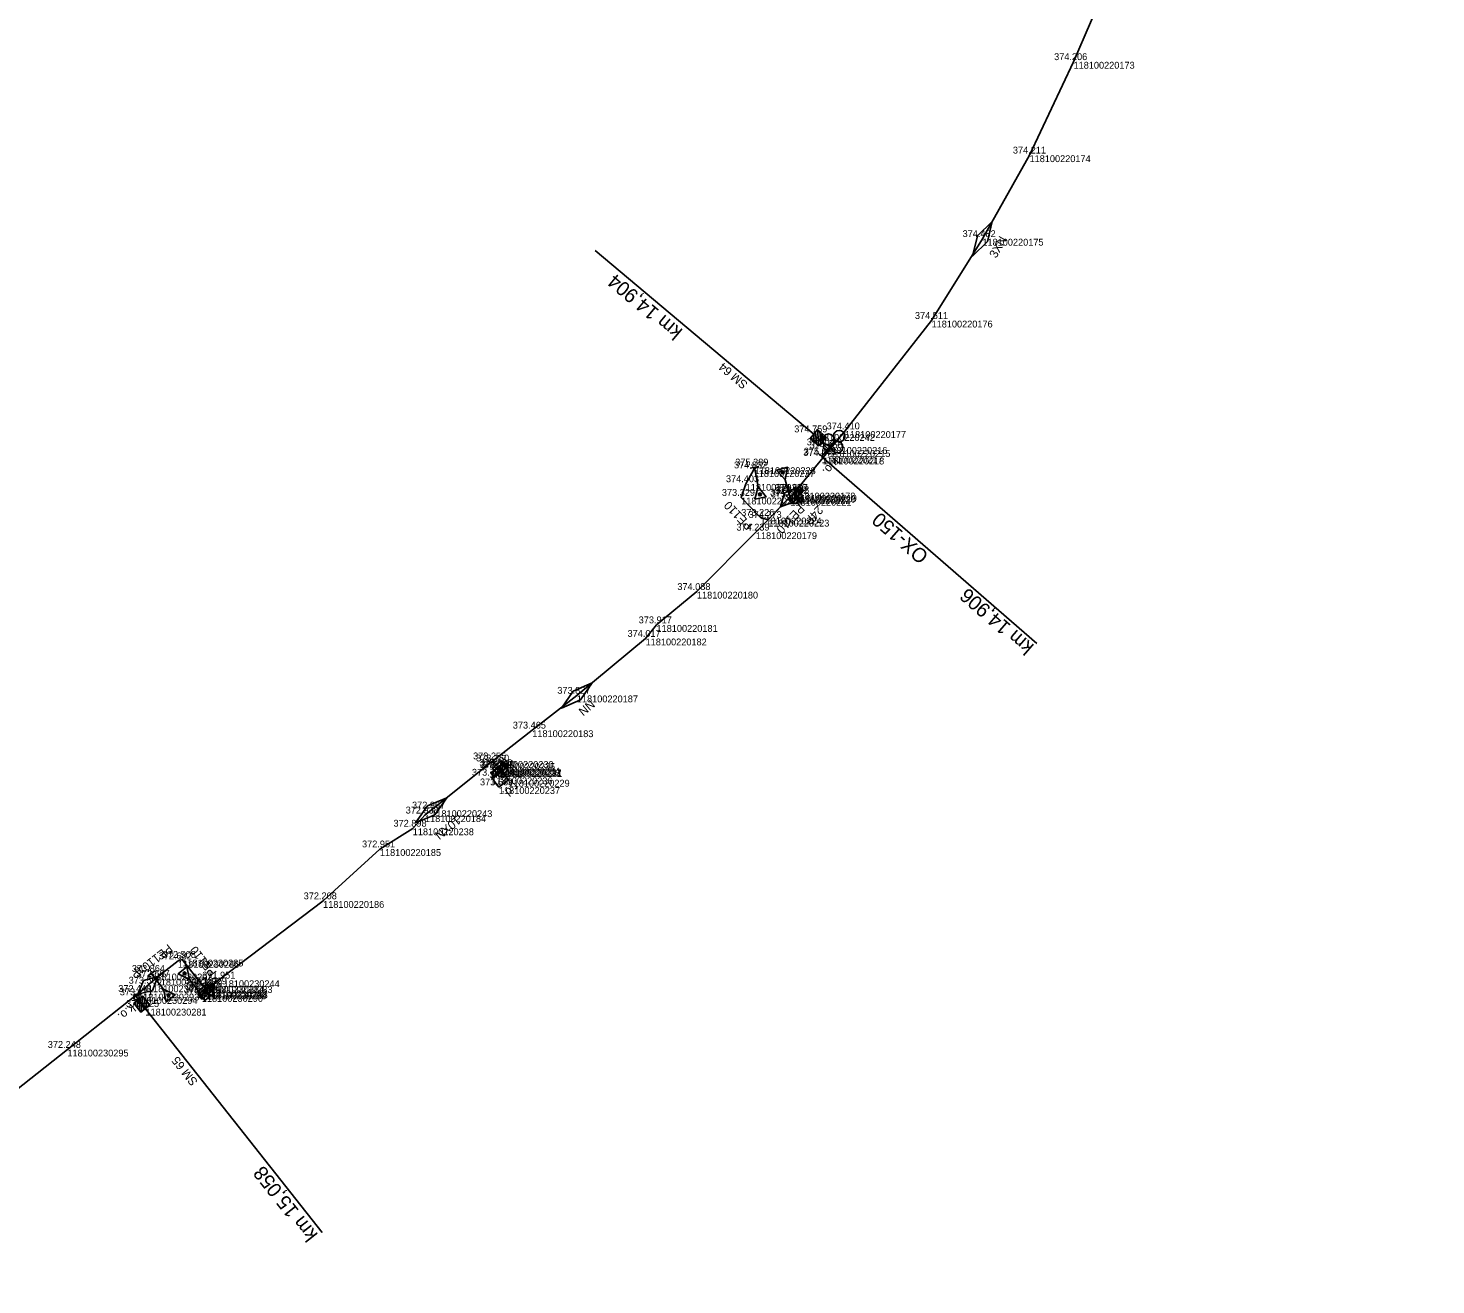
# Model space of a CAD drawing. Extents: x -732194 to -724760, y -944826 to -941477.
# Drawn here: x -731076.7 to -730830.1, y -942059.1 to -941838.8 of the extents above; entities that cross this region are included whole.
import ezdxf

# ---------------------------------------------------------------- set-up
doc = ezdxf.new("R2010")
doc.units = 0
for name, color, linetype in [('Vrstva 26', 7, 'Continuous'), ('Vrstva 28', 7, 'Continuous'), ('Vrstva 3', 7, 'Continuous'), ('Vrstva 31', 7, 'Continuous'), ('Vrstva 33', 7, 'Continuous'), ('Vrstva 35', 7, 'Continuous'), ('Vrstva 36', 7, 'Continuous'), ('Vrstva 4', 7, 'Continuous'), ('Vrstva 60', 7, 'Continuous'), ('Vrstva 61', 7, 'Continuous'), ('Vrstva 8', 7, 'Continuous')]:
    doc.layers.add(name, color=color, linetype=linetype)

msp = doc.modelspace()

# ---------------------------------------------------------------- linework, layer by layer
at = {"layer": 'Vrstva 26'}
for points in [[(-730884.6, -941823.97), (-730893.54, -941844.74), (-730901.25, -941861.12), (-730909.51, -941875.76), (-730918.42, -941890.11), (-730933.6, -941909.47), (-730936.34, -941912.8), (-730937.42, -941914.12), (-730942.48, -941920.27)], [(-730942.48, -941920.27), (-730943.32, -941921.07), (-730947.04, -941925.01), (-730949.2, -941927.21), (-730959.53, -941937.62), (-730966.61, -941943.46), (-730968.52, -941945.84), (-730980.57, -941955.82), (-730988.38, -941961.92), (-730995.35, -941967.32), (-730995.09, -941967.68), (-730994.25, -941968.5), (-730994.17, -941968.84)], [(-730977.88, -941953.59), (-730979.94, -941956.59), (-730983.27, -941958.05), (-730981.21, -941955.05), (-730977.88, -941953.59)]]:
    msp.add_lwpolyline(points, dxfattribs=at)
at = {"layer": 'Vrstva 28'}
for p, q in [((-730936.83, -941912.23), (-730936.89, -941912.3)), ((-730940.92, -941918.54), (-730945.71, -941923.61)), ((-730944.16, -941920.27), (-730941.72, -941919.38)), ((-730941.72, -941919.38), (-730942.47, -941921.87)), ((-730941.75, -941919.41), (-730941.7, -941920.83)), ((-730941.37, -941919.38), (-730941.33, -941920.44)), ((-730944.91, -941922.76), (-730944.16, -941920.27)), ((-730942.47, -941921.87), (-730944.91, -941922.76)), ((-730943.55, -941921.35), (-730943.55, -941921.45)), ((-730943.19, -941920.97), (-730943.16, -941921.81)), ((-730942.83, -941920.58), (-730942.78, -941921.99)), ((-730942.48, -941920.27), (-730942.21, -941920.65)), ((-730942.47, -941920.19), (-730942.42, -941921.6)), ((-730942.11, -941919.8), (-730942.06, -941921.22)), ((-730940.98, -941919.74), (-730940.97, -941920.05)), ((-730994.77, -941968.68), (-730994.93, -941970.09)), ((-730994.36, -941968.35), (-730994.51, -941969.75)), ((-730993.94, -941968.02), (-730994.1, -941969.42)), ((-730993.53, -941967.69), (-730993.69, -941969.09)), ((-730993.16, -941967.71), (-730993.27, -941968.76)), ((-730992.82, -941968.12), (-730992.86, -941968.43)), ((-730995.6, -941969.34), (-730995.61, -941969.44)), ((-730995.19, -941969.01), (-730995.28, -941969.85)), ((-731058.34, -942008.96), (-731053.11, -942004.33)), ((-731056.49, -942005.77), (-731053.98, -942005.1)), ((-731053.98, -942005.1), (-731054.95, -942007.52)), ((-731057.47, -942008.18), (-731056.49, -942005.77)), ((-731054.95, -942007.52), (-731057.47, -942008.18)), ((-731046.86, -942008.2), (-731046.87, -942008.3)), ((-731046.44, -942007.87), (-731046.54, -942008.71)), ((-731046.03, -942007.54), (-731046.19, -942008.95)), ((-731045.61, -942007.21), (-731045.77, -942008.62)), ((-731045.6, -942007.51), (-731045.43, -942007.71)), ((-731045.19, -942006.88), (-731045.36, -942008.29)), ((-731044.78, -942006.56), (-731044.94, -942007.96)), ((-731044.4, -942006.58), (-731044.53, -942007.63)), ((-731044.07, -942007), (-731044.11, -942007.3)), ((-731057.71, -942008.65), (-731057.79, -942008.71)), ((-731057.75, -942008.68), (-731056.16, -942010.73))]:
    msp.add_line(p, q, dxfattribs=at)
for points in [[(-730936.34, -941912.8), (-730933.6, -941909.47), (-730918.42, -941890.11), (-730909.51, -941875.76), (-730901.25, -941861.12), (-730893.54, -941844.74), (-730884.6, -941823.97), (-730884.81, -941823.92), (-730891.53, -941820.91), (-730888.73, -941813.4), (-730882.1, -941797.64), (-730879.51, -941791.69), (-730868.59, -941766.2), (-730855.72, -941741.09), (-730846.98, -941727.15), (-730841.76, -941718.5), (-730840.09, -941716.56), (-730834.08, -941707.22), (-730832.47, -941708.21), (-730830.06, -941709.33)], [(-730937.42, -941914.12), (-730936.34, -941912.8), (-730936.86, -941912.27), (-730939.07, -941909.99)], [(-730943.32, -941921.07), (-730942.48, -941920.27), (-730937.42, -941914.12), (-730937.69, -941913.9)], [(-730947.04, -941925.01), (-730948.39, -941924.63), (-730951.78, -941921.13), (-730950.98, -941918.73), (-730949.59, -941916.31), (-730949.43, -941915.81)], [(-730995.35, -941967.32), (-730988.38, -941961.92), (-730980.57, -941955.82), (-730968.52, -941945.84), (-730966.61, -941943.46), (-730959.53, -941937.62), (-730949.2, -941927.21), (-730947.04, -941925.01), (-730943.32, -941921.07), (-730943.16, -941921.36)], [(-730940.78, -941921.31), (-730941.85, -941920.99), (-730941.46, -941922.04)], [(-731044.61, -942006.77), (-731043.35, -942005.75), (-731025.03, -941991.84), (-731015.08, -941982.75), (-731009.32, -941979.12), (-731007.18, -941976.81), (-731006.09, -941975.94), (-730995.35, -941967.32), (-730995.09, -941967.68), (-730994.25, -941968.5), (-730994.17, -941968.84)], [(-730992.84, -941969.7), (-730993.86, -941969.23), (-730993.63, -941970.32)], [(-731054.37, -942005.45), (-731050.45, -942002.36), (-731049.71, -942002.12), (-731046.09, -942006.71), (-731044.61, -942006.77)], [(-731057.45, -942008.09), (-731055.72, -942006.64), (-731054.37, -942005.45), (-731055.13, -942004.57)], [(-731120.63, -942059.14), (-731119.86, -942058.33), (-731114.37, -942053.86), (-731113.43, -942053.2), (-731112.54, -942052.04), (-731090.85, -942034.48), (-731069.83, -942017.9), (-731057.45, -942008.09), (-731057.75, -942008.68)], [(-731044.61, -942006.77), (-731045.6, -942007.51), (-731046.28, -942008.33)], [(-731044.1, -942008.57), (-731045.12, -942008.1), (-731044.89, -942009.19)]]:
    msp.add_lwpolyline(points, dxfattribs=at)
for points in [[(-730940.82, -941919.89), (-730942.87, -941922.09), (-730943.6, -941921.4), (-730941.56, -941919.21)], [(-730992.69, -941968.29), (-730995.03, -941970.17), (-730995.66, -941969.39), (-730993.31, -941967.51)], [(-731043.94, -942007.17), (-731046.29, -942009.03), (-731046.91, -942008.24), (-731044.56, -942006.38)]]:
    msp.add_lwpolyline(points, close=True, dxfattribs=at)
for centre in [(-730936.86, -941912.27), (-731057.75, -942008.68)]:
    msp.add_circle(centre, 0.5, dxfattribs=at)
at = {"layer": 'Vrstva 3'}
for p, q in [((-730977.36, -941877.83), (-730939.07, -941909.99)), ((-730938.18, -941912.04), (-730938.42, -941909.22)), ((-730937.84, -941911.63), (-730938.02, -941909.56)), ((-730939.4, -941911.01), (-730939.45, -941910.44)), ((-730938.99, -941911.35), (-730939.11, -941910.03)), ((-730938.59, -941911.7), (-730938.77, -941909.63)), ((-730937.5, -941911.22), (-730937.61, -941909.9)), ((-730937.16, -941910.82), (-730937.21, -941910.24)), ((-731057.86, -942009.53), (-731057.93, -942010.1)), ((-731057.45, -942009.2), (-731057.6, -942010.52)), ((-731057.03, -942008.87), (-731057.27, -942010.93)), ((-731056.61, -942008.54), (-731056.94, -942011.35)), ((-731056.29, -942008.96), (-731056.53, -942011.02)), ((-731055.96, -942009.37), (-731056.11, -942010.69)), ((-731055.63, -942009.79), (-731055.69, -942010.36)), ((-731025.19, -942049.98), (-731056.16, -942010.73))]:
    msp.add_line(p, q, dxfattribs=at)
for points in [[(-730939.71, -941910.75), (-730938.42, -941909.22), (-730936.89, -941910.51), (-730938.18, -941912.04)], [(-731055.37, -942010.11), (-731056.94, -942011.35), (-731058.18, -942009.78), (-731056.61, -942008.54)]]:
    msp.add_lwpolyline(points, close=True, dxfattribs=at)
at = {"layer": 'Vrstva 31'}
for points in [[(-730884.6, -941823.97), (-730893.54, -941844.74), (-730901.25, -941861.12), (-730909.51, -941875.76), (-730918.42, -941890.11), (-730933.6, -941909.47), (-730936.34, -941912.8), (-730937.42, -941914.12), (-730942.48, -941920.27), (-730942.41, -941920.81)], [(-730911.23, -941878.8), (-730910.38, -941875.26), (-730907.79, -941872.71), (-730908.64, -941876.25), (-730911.23, -941878.8)], [(-730942.48, -941920.27), (-730943.32, -941921.07), (-730947.04, -941925.01), (-730949.2, -941927.21), (-730959.53, -941937.62), (-730966.61, -941943.46), (-730968.52, -941945.84), (-730980.57, -941955.82), (-730988.38, -941961.92), (-730995.35, -941967.32), (-730995.09, -941967.68), (-730994.25, -941968.5), (-730993.96, -941968.69)], [(-730995.35, -941967.32), (-731006.09, -941975.94), (-731007.18, -941976.81), (-731009.32, -941979.12), (-731015.08, -941982.75), (-731025.03, -941991.84), (-731043.35, -942005.75), (-731044.61, -942006.77), (-731045.6, -942007.51), (-731045.61, -942007.87)], [(-731008.82, -941978.13), (-731006.71, -941975.16), (-731003.36, -941973.75), (-731005.46, -941976.72), (-731008.82, -941978.13)], [(-731044.61, -942006.77), (-731046.09, -942006.71), (-731049.71, -942002.12), (-731050.45, -942002.36), (-731054.37, -942005.45), (-731055.72, -942006.64), (-731057.45, -942008.09)], [(-731057.45, -942008.09), (-731069.83, -942017.9), (-731090.85, -942034.48), (-731112.54, -942052.04), (-731113.43, -942053.2), (-731114.37, -942053.86), (-731119.86, -942058.33), (-731120.63, -942059.14)]]:
    msp.add_lwpolyline(points, dxfattribs=at)
at = {"layer": 'Vrstva 33'}
for p, q in [((-730942.03, -941921.14), (-730942.78, -941920.47)), ((-730941.7, -941920.77), (-730942.37, -941921.52)), ((-730993.65, -941969.08), (-730994.28, -941968.3)), ((-730993.26, -941968.77), (-730994.04, -941969.39)), ((-731045.3, -942008.26), (-731045.92, -942007.48)), ((-731044.91, -942007.95), (-731045.69, -942008.57))]:
    msp.add_line(p, q, dxfattribs=at)
for points in [[(-730940.99, -941920.74), (-730942.33, -941922.22), (-730943.82, -941920.88), (-730942.48, -941919.4), (-730940.99, -941920.74)], [(-730992.56, -941968.84), (-730994.12, -941970.1), (-730995.37, -941968.54), (-730993.81, -941967.28), (-730992.56, -941968.84)], [(-731044.21, -942008.04), (-731045.78, -942009.28), (-731047.02, -942007.71), (-731045.45, -942006.47), (-731044.21, -942008.04)]]:
    msp.add_lwpolyline(points, dxfattribs=at)
at = {"layer": 'Vrstva 35'}
for p, q in [((-730948.39, -941924.63), (-730951.78, -941921.13)), ((-730947.04, -941925.01), (-730943.32, -941921.07)), ((-731054.37, -942005.45), (-731050.45, -942002.36)), ((-731049.71, -942002.12), (-731046.09, -942006.71))]:
    msp.add_line(p, q, dxfattribs=at)
at = {"layer": 'Vrstva 36'}
msp.add_lwpolyline([(-730993.85, -941968.89), (-730995.54, -941970.18), (-730994.22, -941971.88), (-730992.54, -941970.6)], close=True, dxfattribs=at)
at = {"layer": 'Vrstva 4'}
for p, q in [((-730948.66, -941915.67), (-730950.19, -941915.96)), ((-730944.61, -941916.92), (-730944.36, -941916.49)), ((-730948.34, -941920.36), (-730948.62, -941920.76)), ((-730943.91, -941921.57), (-730942.41, -941921.16)), ((-731054.52, -942004.09), (-731055.74, -942005.05)), ((-731049.33, -942004.79), (-731049.27, -942004.3)), ((-731052.08, -942008.12), (-731052.14, -942008.6)), ((-731046.89, -942008.81), (-731045.66, -942007.85))]:
    msp.add_line(p, q, dxfattribs=at)
for points in [[(-730949.43, -941915.81), (-730948.77, -941919.23), (-730947.42, -941921.01), (-730949.38, -941921.39), (-730948.77, -941919.23)], [(-730943.16, -941921.36), (-730944.09, -941918.01), (-730945.58, -941916.34), (-730943.65, -941915.8), (-730944.09, -941918.01)], [(-731055.13, -942004.57), (-731052.98, -942007.31), (-731050.96, -942008.27), (-731052.53, -942009.51), (-731052.98, -942007.31)], [(-731046.28, -942008.33), (-731048.43, -942005.6), (-731050.44, -942004.63), (-731048.88, -942003.39), (-731048.43, -942005.6)]]:
    msp.add_lwpolyline(points, dxfattribs=at)
for centre in [(-730944.48, -941916.71), (-730948.48, -941920.56), (-731049.3, -942004.54), (-731052.11, -942008.36)]:
    msp.add_circle(centre, 0.248, dxfattribs=at)
at = {"layer": 'Vrstva 60'}
for p, q in [((-730893.54, -941844.74), (-730893.54, -941844.74)), ((-730901.25, -941861.12), (-730901.25, -941861.12)), ((-730909.51, -941875.76), (-730909.51, -941875.76)), ((-730918.42, -941890.11), (-730918.42, -941890.11)), ((-730933.6, -941909.47), (-730933.6, -941909.47)), ((-730939.07, -941909.99), (-730939.07, -941909.99)), ((-730937.69, -941913.9), (-730937.69, -941913.9)), ((-730937.42, -941914.12), (-730937.42, -941914.12)), ((-730936.86, -941912.27), (-730936.86, -941912.27)), ((-730936.34, -941912.8), (-730936.34, -941912.8)), ((-730949.59, -941916.31), (-730949.59, -941916.31)), ((-730949.43, -941915.81), (-730949.43, -941915.81)), ((-730950.98, -941918.73), (-730950.98, -941918.73)), ((-730951.78, -941921.13), (-730951.78, -941921.13)), ((-730943.32, -941921.07), (-730943.32, -941921.07)), ((-730943.16, -941921.36), (-730943.16, -941921.36)), ((-730942.48, -941920.27), (-730942.48, -941920.27)), ((-730942.41, -941920.81), (-730942.41, -941920.81)), ((-730942.21, -941920.65), (-730942.21, -941920.65)), ((-730948.39, -941924.63), (-730948.39, -941924.63)), ((-730947.04, -941925.01), (-730947.04, -941925.01)), ((-730949.2, -941927.21), (-730949.2, -941927.21)), ((-730959.53, -941937.62), (-730959.53, -941937.62)), ((-730966.61, -941943.46), (-730966.61, -941943.46)), ((-730968.52, -941945.84), (-730968.52, -941945.84)), ((-730980.57, -941955.82), (-730980.57, -941955.82)), ((-730988.38, -941961.92), (-730988.38, -941961.92)), ((-730995.35, -941967.32), (-730995.35, -941967.32)), ((-730995.09, -941967.68), (-730995.09, -941967.68)), ((-730994.25, -941968.5), (-730994.25, -941968.5)), ((-730993.96, -941968.69), (-730993.96, -941968.69)), ((-730995.54, -941970.18), (-730995.54, -941970.18)), ((-730994.17, -941968.84), (-730994.17, -941968.84)), ((-730993.85, -941968.89), (-730993.85, -941968.89)), ((-730992.54, -941970.6), (-730992.54, -941970.6)), ((-730994.22, -941971.88), (-730994.22, -941971.88)), ((-731006.09, -941975.94), (-731006.09, -941975.94)), ((-731007.18, -941976.81), (-731007.18, -941976.81)), ((-731009.32, -941979.12), (-731009.32, -941979.12)), ((-731015.08, -941982.75), (-731015.08, -941982.75)), ((-731025.03, -941991.84), (-731025.03, -941991.84)), ((-731050.45, -942002.36), (-731050.45, -942002.36)), ((-731049.71, -942002.12), (-731049.71, -942002.12)), ((-731055.13, -942004.57), (-731055.13, -942004.57)), ((-731054.37, -942005.45), (-731054.37, -942005.45)), ((-731043.35, -942005.75), (-731043.35, -942005.75)), ((-731057.45, -942008.09), (-731057.45, -942008.09)), ((-731055.72, -942006.64), (-731055.72, -942006.64)), ((-731046.09, -942006.71), (-731046.09, -942006.71)), ((-731045.61, -942007.87), (-731045.61, -942007.87)), ((-731045.6, -942007.51), (-731045.6, -942007.51)), ((-731045.43, -942007.71), (-731045.43, -942007.71)), ((-731044.61, -942006.77), (-731044.61, -942006.77)), ((-731057.75, -942008.68), (-731057.75, -942008.68)), ((-731046.28, -942008.33), (-731046.28, -942008.33)), ((-731056.16, -942010.73), (-731056.16, -942010.73)), ((-731069.83, -942017.9), (-731069.83, -942017.9))]:
    msp.add_line(p, q, dxfattribs=at)
at = {"layer": 'Vrstva 8'}
for p, q in [((-730937.69, -941913.9), (-730935.72, -941911.64)), ((-730938.25, -941913.41), (-730937.12, -941914.39)), ((-730899.96, -941946.71), (-730937.69, -941913.9))]:
    msp.add_line(p, q, dxfattribs=at)
for centre in [(-730934.6, -941910.36), (-730936.47, -941910.98), (-730934.96, -941912.29)]:
    msp.add_circle(centre, 1, dxfattribs=at)

# ---------------------------------------------------------------- texts
at = {"layer": 'Vrstva 26'}
msp.add_text('NN', height=1.5, rotation=219.6021, dxfattribs=at).set_placement((-730978.19, -941956.5))
at = {"layer": 'Vrstva 28'}
for s, rotation, p in [('k.o.', 229.9827, (-730935.56, -941913.97)), ('24P', 226.6071, (-730938.35, -941922.43)), ('4P', 221.46, (-731057.07, -942002.85)), ('k.o.', 218.2737, (-731058.63, -942009.8))]:
    msp.add_text(s, height=1.5, rotation=rotation, dxfattribs=at).set_placement(p)
at = {"layer": 'Vrstva 3'}
for s, height, rotation, p in [('km 14,904', 2.5, 139.9827, (-730961.87, -941891.79)), ('SM 64', 1.5, 139.9827, (-730950.49, -941901.08)), ('SM 65', 1.5, 128.3334, (-731046.91, -942023.49)), ('km 15,058', 2.5, 128.3334, (-731025.82, -942050.32))]:
    msp.add_text(s, height=height, rotation=rotation, dxfattribs=at).set_placement(p)
at = {"layer": 'Vrstva 31'}
for s, rotation, p in [('3XN', 60.56, (-730907.1, -941879.27)), ('10XN', 218.7347, (-731001.67, -941976.89))]:
    msp.add_text(s, height=1.5, rotation=rotation, dxfattribs=at).set_placement(p)
at = {"layer": 'Vrstva 36'}
for s, rotation, p in [('PE110', 134.0938, (-730949.68, -941925.94)), ('PE110', 226.6071, (-730941.59, -941922.19)), ('r.d.', 217.2762, (-730991.46, -941971.02)), ('PE110', 218.2612, (-731052.17, -941999.32)), ('PE110', 128.2894, (-731043.6, -942004.33))]:
    msp.add_text(s, height=1.5, rotation=rotation, dxfattribs=at).set_placement(p)
at = {"layer": 'Vrstva 60'}
for s, p in [('118100220173', (-730893.54, -941845.94)), ('118100220174', (-730901.25, -941862.32)), ('118100220175', (-730909.51, -941876.96)), ('118100220176', (-730918.42, -941891.31)), ('118100220177', (-730933.6, -941910.67)), ('118100220242', (-730939.07, -941911.19)), ('118100220217', (-730937.69, -941915.1)), ('118100220218', (-730937.42, -941915.32)), ('118100220216', (-730936.86, -941913.47)), ('118100220215', (-730936.34, -941914)), ('118100220227', (-730949.59, -941917.51)), ('118100220228', (-730949.43, -941917.01)), ('118100220226', (-730950.98, -941919.93)), ('118100220225', (-730951.78, -941922.33)), ('118100220222', (-730943.32, -941922.27)), ('118100220221', (-730943.16, -941922.56)), ('118100220178', (-730942.48, -941921.47)), ('118100220220', (-730942.41, -941922.01)), ('118100220219', (-730942.21, -941921.85)), ('118100220224', (-730948.39, -941925.83)), ('118100220223', (-730947.04, -941926.21)), ('118100220179', (-730949.2, -941928.41)), ('118100220180', (-730959.53, -941938.83)), ('118100220181', (-730966.61, -941944.67)), ('118100220182', (-730968.52, -941947.04)), ('118100220187', (-730980.57, -941957.02)), ('118100220183', (-730988.38, -941963.12)), ('118100220230', (-730995.35, -941968.52)), ('118100220235', (-730995.09, -941968.88)), ('118100220234', (-730994.25, -941969.7)), ('118100220232', (-730993.96, -941969.89)), ('118100220236', (-730995.54, -941971.38)), ('118100220233', (-730994.17, -941970.04)), ('118100220231', (-730993.85, -941970.09)), ('118100220229', (-730992.54, -941971.8)), ('118100220237', (-730994.22, -941973.08)), ('118100220243', (-731006.09, -941977.14)), ('118100220184', (-731007.18, -941978.01)), ('118100220238', (-731009.32, -941980.32)), ('118100220185', (-731015.08, -941983.95)), ('118100220186', (-731025.03, -941993.05)), ('118100230286', (-731050.45, -942003.56)), ('118100230285', (-731049.71, -942003.32)), ('118100230292', (-731055.13, -942005.77)), ('118100230287', (-731054.37, -942006.65)), ('118100230244', (-731043.35, -942006.95)), ('118100230293', (-731057.45, -942009.29)), ('118100230291', (-731055.72, -942007.84)), ('118100230284', (-731046.09, -942007.91)), ('118100230289', (-731045.61, -942009.07)), ('118100230282', (-731045.6, -942008.71)), ('118100230288', (-731045.43, -942008.91)), ('118100230283', (-731044.61, -942007.97)), ('118100230294', (-731057.75, -942009.88)), ('118100230290', (-731046.28, -942009.53)), ('118100230281', (-731056.16, -942011.93)), ('118100230295', (-731069.83, -942019.1))]:
    msp.add_text(s, height=1.2, dxfattribs=at).set_placement(p)
at = {"layer": 'Vrstva 61'}
for s, p in [('374.206', (-730896.94, -941844.44)), ('374.211', (-730904.17, -941860.82)), ('374.482', (-730912.98, -941875.46)), ('374.511', (-730921.33, -941889.81)), ('374.759', (-730942.48, -941909.69)), ('374.410', (-730936.8, -941909.17)), ('375.043', (-730940.29, -941911.97)), ('374.456', (-730939.78, -941912.5)), ('375.389', (-730952.81, -941915.51)), ('374.477', (-730940.89, -941913.82)), ('375.061', (-730940.8, -941913.6)), ('374.832', (-730953.03, -941916.01)), ('374.403', (-730954.44, -941918.43)), ('374.607', (-730945.89, -941919.97)), ('374.942', (-730945.84, -941920.51)), ('374.943', (-730945.65, -941920.35)), ('373.329', (-730955.16, -941920.83)), ('374.262', (-730946.72, -941920.77)), ('375.047', (-730946.59, -941921.06)), ('373.226', (-730951.77, -941924.33)), ('374.273', (-730950.48, -941924.71)), ('374.239', (-730952.61, -941926.91)), ('374.088', (-730962.96, -941937.33)), ('373.917', (-730969.73, -941943.17)), ('374.017', (-730971.69, -941945.54)), ('373.827', (-730983.99, -941955.52)), ('373.465', (-730991.79, -941961.62)), ('373.255', (-730998.75, -941967.02)), ('373.150', (-730998.23, -941967.38)), ('373.773', (-730998.95, -941969.88)), ('373.300', (-730997.65, -941968.2)), ('373.703', (-730997.58, -941968.54)), ('373.734', (-730997.41, -941968.39)), ('373.817', (-730997, -941968.59)), ('373.669', (-730997.54, -941971.58)), ('373.766', (-730995.89, -941970.3)), ('372.938', (-731010.56, -941976.51)), ('372.967', (-731009.45, -941975.64)), ('372.898', (-731012.7, -941978.82)), ('372.951', (-731018.21, -941982.45)), ('372.208', (-731028.43, -941991.55)), ('372.508', (-731053.12, -942001.82)), ('373.864', (-731058.54, -942004.27)), ('372.682', (-731053.83, -942002.06)), ('373.560', (-731059.1, -942006.34)), ('372.667', (-731057.72, -942005.15)), ('372.182', (-731049.24, -942006.41)), ('371.929', (-731047.7, -942006.47)), ('371.951', (-731046.21, -942005.45)), ('372.448', (-731060.92, -942007.79)), ('373.171', (-731060.65, -942008.38)), ('373.156', (-731049.4, -942008.03)), ('372.397', (-731048.98, -942007.21)), ('372.912', (-731048.73, -942007.57)), ('372.918', (-731048.55, -942007.41)), ('373.525', (-731059.57, -942010.43)), ('372.248', (-731073.27, -942017.6))]:
    msp.add_text(s, height=1.2, dxfattribs=at).set_placement(p)
at = {"layer": 'Vrstva 8'}
for s, p in [('OX-150', (-730918.77, -941931.09)), ('km 14,906', (-730900.3, -941947.06))]:
    msp.add_text(s, height=2.5, rotation=138.9854, dxfattribs=at).set_placement(p)

doc.saveas('drawing.dxf')
